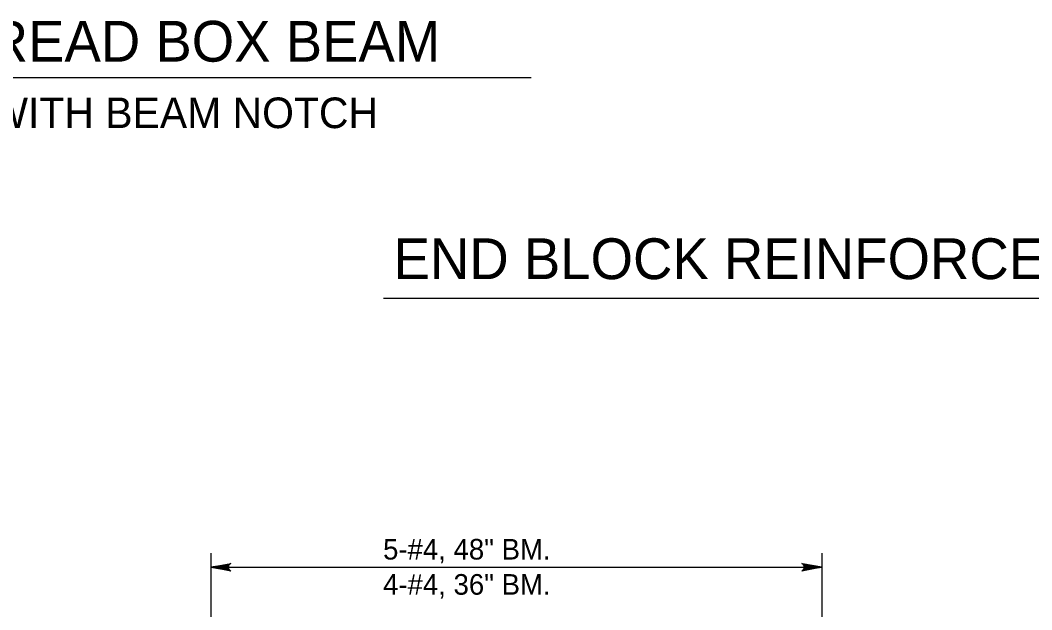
# Model space of a CAD drawing. Extents: x 639331 to 643089, y 299088 to 300975.
# Drawn here: x 641530.2 to 641679, y 299248.4 to 299335.1 of the extents above; entities that cross this region are included whole.
import ezdxf

# ---------------------------------------------------------------- set-up
doc = ezdxf.new("R2010")
doc.units = 0
doc.layers.add('1', color=7, linetype='Continuous')

msp = doc.modelspace()

# ---------------------------------------------------------------- linework, layer by layer
at = {"layer": '1'}
for p, q in [((641605.31, 299326.64), (641513.06, 299326.64)), ((641721.86, 299294.19), (641583.61, 299294.19)), ((641558.17, 299256.75), (641558.17, 299244.44)), ((641648.09, 299256.75), (641648.09, 299225.23)), ((641558.17, 299254.7), (641648.09, 299254.7))]:
    msp.add_line(p, q, dxfattribs=at)
for points in [[(641558.17, 299254.7), (641561.15, 299255.26), (641561.03, 299255.18), (641560.92, 299255.1), (641560.86, 299255), (641560.8, 299254.9), (641560.78, 299254.8), (641560.77, 299254.7), (641560.78, 299254.6), (641560.8, 299254.5), (641560.86, 299254.4), (641560.92, 299254.3), (641561.03, 299254.22), (641561.15, 299254.14), (641558.17, 299254.7), (641561.03, 299254.22), (641560.92, 299254.3), (641558.17, 299254.7), (641560.86, 299254.4), (641560.8, 299254.5), (641558.17, 299254.7), (641560.78, 299254.6), (641560.77, 299254.7), (641558.17, 299254.7), (641560.78, 299254.8), (641560.8, 299254.9), (641558.17, 299254.7), (641560.86, 299255), (641560.92, 299255.1), (641558.17, 299254.7), (641561.03, 299255.18)], [(641648.09, 299254.7), (641645.11, 299254.14), (641645.22, 299254.22), (641645.34, 299254.3), (641645.39, 299254.4), (641645.45, 299254.5), (641645.47, 299254.6), (641645.49, 299254.7), (641645.47, 299254.8), (641645.45, 299254.9), (641645.39, 299255), (641645.34, 299255.1), (641645.22, 299255.18), (641645.11, 299255.26), (641648.09, 299254.7), (641645.22, 299255.18), (641645.34, 299255.1), (641648.09, 299254.7), (641645.39, 299255), (641645.45, 299254.9), (641648.09, 299254.7), (641645.47, 299254.8), (641645.49, 299254.7), (641648.09, 299254.7), (641645.47, 299254.6), (641645.45, 299254.5), (641648.09, 299254.7), (641645.39, 299254.4), (641645.34, 299254.3), (641648.09, 299254.7), (641645.22, 299254.22)]]:
    msp.add_lwpolyline(points, dxfattribs=at)

# ---------------------------------------------------------------- texts
for s, height, p in [('SPREAD BOX BEAM', 6, (641514.81, 299329.02)), ('WITH BEAM NOTCH', 4.5, (641525.62, 299319.25)), ('END BLOCK REINFORCEMENT', 6, (641585.07, 299297.05))]:
    msp.add_text(s, height=height, rotation=360, dxfattribs=at).set_placement(p)
for s, p in [('5-#4, 48" BM.', (641583.53, 299255.83)), ('4-#4, 36" BM.', (641583.53, 299250.66))]:
    msp.add_text(s, height=3.0311, dxfattribs=at).set_placement(p)

doc.saveas('drawing.dxf')
